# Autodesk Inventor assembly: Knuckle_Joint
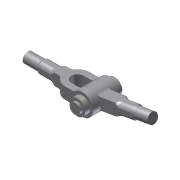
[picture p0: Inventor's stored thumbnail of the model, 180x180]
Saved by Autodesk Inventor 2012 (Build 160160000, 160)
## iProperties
Created: 2011-09
Part Number: Knuckle_Joint
Document SubType Name: Assembly
Designer: CADCIM
Author: CADCIM
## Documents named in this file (6)
- C:\SANDEEP\Inventor_Mechine_Design\Joints\Knuckle_joint\Knuckle_Joint.iam
- C:\SANDEEP\Inventor_Mechine_Design\Joints\Knuckle_joint\Fork_End_A.ipt
- C:\SANDEEP\Inventor_Mechine_Design\Joints\Knuckle_joint\Eye_End_B.ipt
- C:\SANDEEP\Inventor_Mechine_Design\Joints\Knuckle_joint\Pin.ipt
- C:\SANDEEP\Inventor_Mechine_Design\Joints\Knuckle_joint\Coller.ipt
- C:\SANDEEP\Inventor_Mechine_Design\Joints\Knuckle_joint\Taper_Pin.ipt
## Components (5 placed, 5 different names)
1. Fork_End_A:1 — Insert:1, Mate:1, Mate:2
2. Eye_End_B:1 — Insert:1
3. Pin:1 — Mate:1, Mate:2, Mate:3, Mate:4
4. Coller:1 — Mate:3, Mate:4, Mate:5
5. Taper_Pin:1 — Mate:5
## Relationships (6: Mate 5, Insert 1)
- Insert:1: Fork_End_A:1 ↔ Eye_End_B:1
- Mate:1: Fork_End_A:1 ↔ Pin:1
- Mate:2: Fork_End_A:1 ↔ Pin:1
- Mate:3: Pin:1 ↔ Coller:1
- Mate:4: Pin:1 ↔ Coller:1
- Mate:5: Coller:1 ↔ Taper_Pin:1
